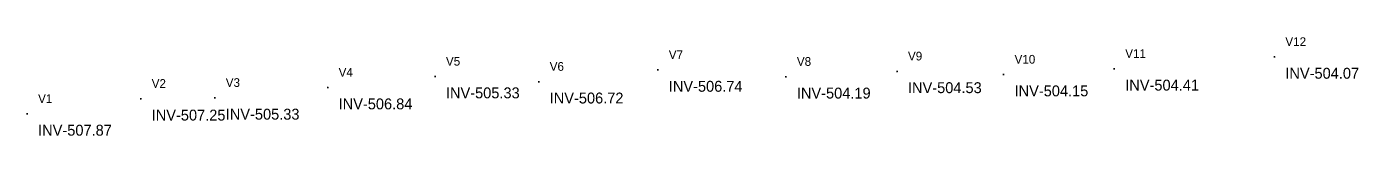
# Model space of a CAD drawing. Extents: x 1749700 to 1750311, y 652756 to 652801.
import ezdxf

# ---------------------------------------------------------------- set-up
doc = ezdxf.new("R2010")
doc.units = 0
for name, color, linetype in [('SURVEY - DRAINAGE - Storm Sewer - Points - Elevations', 7, 'Continuous'), ('SURVEY - DRAINAGE - Storm Sewer - Points - Locators', 7, 'Continuous'), ('SURVEY - DRAINAGE - Storm Sewer - Points - Numbers', 7, 'Continuous')]:
    doc.layers.add(name, color=color, linetype=linetype)

msp = doc.modelspace()

# ---------------------------------------------------------------- linework, layer by layer
at = {"layer": 'SURVEY - DRAINAGE - Storm Sewer - Points - Locators'}
for p, q in [((1750272.76, 652791.91), (1750272.26, 652791.91)), ((1750272.51, 652791.66), (1750272.51, 652792.16)), ((1750272.51, 652791.91), (1750272.51, 652791.91)), ((1750272.51, 652791.91), (1750272.51, 652791.91)), ((1749990.06, 652785.93), (1749989.56, 652785.93)), ((1749989.81, 652785.68), (1749989.81, 652786.18)), ((1749989.81, 652785.93), (1749989.81, 652785.93)), ((1749989.81, 652785.93), (1749989.81, 652785.93)), ((1750099.48, 652785.04), (1750099.48, 652785.54)), ((1750199.35, 652786.46), (1750198.85, 652786.46)), ((1750199.1, 652786.21), (1750199.1, 652786.71)), ((1750199.1, 652786.46), (1750199.1, 652786.46)), ((1750199.1, 652786.46), (1750199.1, 652786.46)), ((1749887.88, 652782.91), (1749887.38, 652782.91)), ((1749887.63, 652782.66), (1749887.63, 652783.16)), ((1749887.63, 652782.91), (1749887.63, 652782.91)), ((1749887.63, 652782.91), (1749887.63, 652782.91)), ((1749935.46, 652780.54), (1749934.96, 652780.54)), ((1749935.21, 652780.29), (1749935.21, 652780.79)), ((1749935.21, 652780.54), (1749935.21, 652780.54)), ((1749935.21, 652780.54), (1749935.21, 652780.54)), ((1750048.79, 652782.81), (1750048.29, 652782.81)), ((1750048.54, 652782.56), (1750048.54, 652783.06)), ((1750048.54, 652782.81), (1750048.54, 652782.81)), ((1750048.54, 652782.81), (1750048.54, 652782.81)), ((1750099.73, 652785.29), (1750099.23, 652785.29)), ((1750099.48, 652785.29), (1750099.48, 652785.29)), ((1750099.48, 652785.29), (1750099.48, 652785.29)), ((1750148.6, 652783.82), (1750148.1, 652783.82)), ((1750148.35, 652783.57), (1750148.35, 652784.07)), ((1750148.35, 652783.82), (1750148.35, 652783.82)), ((1750148.35, 652783.82), (1750148.35, 652783.82)), ((1749786.67, 652772.88), (1749786.67, 652773.38)), ((1749838.68, 652777.85), (1749838.18, 652777.85)), ((1749838.43, 652777.6), (1749838.43, 652778.1)), ((1749838.43, 652777.85), (1749838.43, 652777.85)), ((1749838.43, 652777.85), (1749838.43, 652777.85)), ((1749752.97, 652772.71), (1749752.47, 652772.71)), ((1749752.72, 652772.46), (1749752.72, 652772.96)), ((1749752.72, 652772.71), (1749752.72, 652772.71)), ((1749752.72, 652772.71), (1749752.72, 652772.71)), ((1749786.92, 652773.13), (1749786.42, 652773.13)), ((1749786.67, 652773.13), (1749786.67, 652773.13)), ((1749786.67, 652773.13), (1749786.67, 652773.13)), ((1749700.88, 652765.77), (1749700.38, 652765.77)), ((1749700.63, 652765.52), (1749700.63, 652766.02)), ((1749700.63, 652765.77), (1749700.63, 652765.77)), ((1749700.63, 652765.77), (1749700.63, 652765.77))]:
    msp.add_line(p, q, dxfattribs=at)

# ---------------------------------------------------------------- texts
at = {"layer": 'SURVEY - DRAINAGE - Storm Sewer - Points - Elevations'}
for s, p in [('INV-504.07', (1750277.51, 652781.91)), ('INV-506.74', (1749994.81, 652775.93)), ('INV-504.53', (1750104.48, 652775.29)), ('INV-504.41', (1750204.1, 652776.46)), ('INV-505.33', (1749892.63, 652772.91)), ('INV-506.72', (1749940.21, 652770.54)), ('INV-504.19', (1750053.54, 652772.81)), ('INV-504.15', (1750153.35, 652773.82)), ('INV-507.25', (1749757.72, 652762.71)), ('INV-505.33', (1749791.67, 652763.13)), ('INV-506.84', (1749843.43, 652767.85)), ('INV-507.87', (1749705.63, 652755.77))]:
    msp.add_text(s, height=5, dxfattribs=at).set_placement(p)
at = {"layer": 'SURVEY - DRAINAGE - Storm Sewer - Points - Numbers'}
for s, p in [('V12', (1750277.51, 652796.91)), ('V5', (1749892.63, 652787.91)), ('V7', (1749994.81, 652790.93)), ('V8', (1750053.54, 652787.81)), ('V9', (1750104.48, 652790.29)), ('V10', (1750153.35, 652788.82)), ('V11', (1750204.1, 652791.46)), ('V4', (1749843.43, 652782.85)), ('V6', (1749940.21, 652785.54)), ('V2', (1749757.72, 652777.71)), ('V3', (1749791.67, 652778.13)), ('V1', (1749705.63, 652770.77))]:
    msp.add_text(s, height=4, dxfattribs=at).set_placement(p)

doc.saveas('drawing.dxf')
